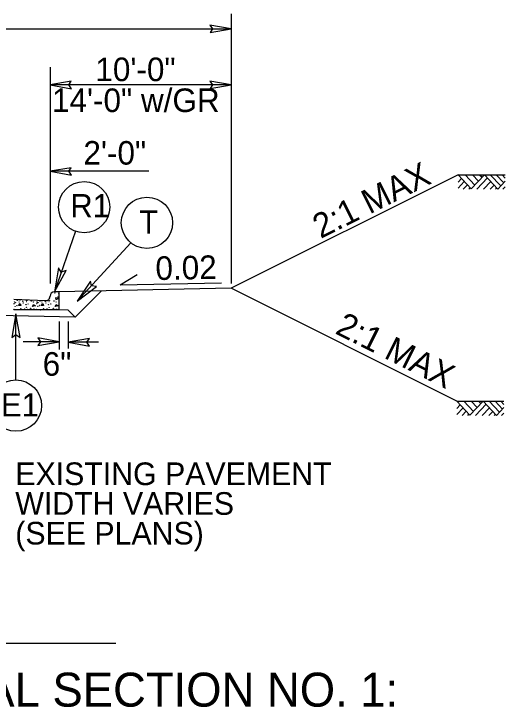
# Model space of a CAD drawing. Extents: x 1904401 to 1905163, y 193929 to 194736.
# Drawn here: x 1904816.27 to 1904843.39, y 194578.77 to 194617.01 of the extents above; entities that cross this region are included whole.
import ezdxf

# ---------------------------------------------------------------- set-up
doc = ezdxf.new("R2010")
doc.units = 0
for name, color, linetype in [('Old_Level_1', 7, 'Continuous'), ('Old_Level_11', 7, 'Continuous'), ('Old_Level_20', 7, 'Continuous'), ('Prop Dimension Text', 7, 'Continuous'), ('Prop Lane Arrow CELL', 7, 'Continuous'), ('Typical Arrow Superelevation CELL', 7, 'Continuous'), ('Typical Berm CELL', 7, 'Continuous'), ('Typical Curb CELL', 7, 'Continuous'), ('Typical Hinge Slope Arterial CELL', 7, 'Continuous'), ('Typical Pavement Slope CELL', 7, 'Continuous'), ('Typical Terminator CELL', 7, 'Continuous')]:
    doc.layers.add(name, color=color, linetype=linetype)

msp = doc.modelspace()

# ---------------------------------------------------------------- linework, layer by layer
at = {"layer": 'Old_Level_1'}
for p, q in [((1904764.772, 194616.184), (1904828.272, 194616.184)), ((1904828.272, 194613.092), (1904818.272, 194613.092)), ((1904823.719, 194608.326), (1904818.272, 194608.326)), ((1904840.792, 194608.132), (1904841.516, 194607.353)), ((1904841.184, 194608.14), (1904841.716, 194607.567)), ((1904841.516, 194607.353), (1904842.247, 194608.139)), ((1904841.582, 194608.14), (1904841.914, 194607.781)), ((1904841.826, 194607.335), (1904842.413, 194607.963)), ((1904841.983, 194608.14), (1904842.117, 194607.997)), ((1904842.247, 194608.139), (1904842.988, 194607.343)), ((1904842.569, 194608.14), (1904843.15, 194607.517)), ((1904842.902, 194608.14), (1904843.317, 194607.696)), ((1904843.223, 194608.14), (1904843.393, 194607.957)), ((1904840.792, 194607.731), (1904840.978, 194607.931)), ((1904840.792, 194607.398), (1904841.135, 194607.764)), ((1904841.081, 194607.335), (1904841.307, 194607.578)), ((1904842.196, 194607.335), (1904842.596, 194607.764)), ((1904842.562, 194607.335), (1904842.78, 194607.568)), ((1904842.988, 194607.343), (1904843.392, 194607.778)), ((1904841.391, 194607.335), (1904841.463, 194607.411)), ((1904842.857, 194607.335), (1904842.927, 194607.409)), ((1904843.258, 194607.335), (1904843.393, 194607.478)), ((1904840.725, 194595.646), (1904841.449, 194594.867)), ((1904840.725, 194595.245), (1904840.911, 194595.445)), ((1904841.116, 194595.654), (1904841.649, 194595.081)), ((1904841.449, 194594.867), (1904842.18, 194595.653)), ((1904841.514, 194595.654), (1904841.847, 194595.295)), ((1904841.759, 194594.849), (1904842.345, 194595.477)), ((1904841.916, 194595.654), (1904842.049, 194595.511)), ((1904842.18, 194595.653), (1904842.921, 194594.857)), ((1904842.502, 194595.654), (1904843.082, 194595.031)), ((1904842.835, 194595.654), (1904843.249, 194595.21)), ((1904843.155, 194595.654), (1904843.325, 194595.471)), ((1904840.725, 194594.912), (1904841.067, 194595.278)), ((1904841.013, 194594.849), (1904841.24, 194595.092)), ((1904842.129, 194594.849), (1904842.529, 194595.278)), ((1904842.495, 194594.849), (1904842.712, 194595.082)), ((1904842.921, 194594.857), (1904843.325, 194595.292)), ((1904843.191, 194594.849), (1904843.325, 194594.992)), ((1904841.324, 194594.849), (1904841.395, 194594.925)), ((1904842.79, 194594.849), (1904842.859, 194594.923)), ((1904769.505, 194582.305), (1904821.899, 194582.305))]:
    msp.add_line(p, q, dxfattribs=at)
for points in [[(1904840.792, 194608.14), (1904843.392, 194608.14)], [(1904840.725, 194595.654), (1904843.325, 194595.654)]]:
    msp.add_lwpolyline(points, dxfattribs=at)
at = {"layer": 'Old_Level_11'}
for p, q in [((1904819.679, 194605.019), (1904818.512, 194601.682)), ((1904822.732, 194604.386), (1904819.776, 194601.157)), ((1904816.389, 194596.816), (1904816.389, 194600.471))]:
    msp.add_line(p, q, dxfattribs=at)
for points in [[(1904818.729, 194602.993), (1904818.512, 194601.682), (1904819.164, 194602.849), (1904818.889, 194602.768)], [(1904820.501, 194602.27), (1904819.776, 194601.157), (1904820.841, 194601.964), (1904820.557, 194602)], [(1904816.615, 194599.161), (1904816.389, 194600.471), (1904816.156, 194599.155), (1904816.389, 194599.322)]]:
    msp.add_lwpolyline(points, close=True, dxfattribs=at)
for centre in [(1904820.156, 194606.35), (1904823.62, 194605.487), (1904816.389, 194595.402)]:
    msp.add_circle(centre, 1.414, dxfattribs=at)
at = {"layer": 'Prop Dimension Text'}
for p, q in [((1904828.272, 194617.012), (1904828.272, 194602.146)), ((1904818.272, 194614.065), (1904818.272, 194602.146))]:
    msp.add_line(p, q, dxfattribs=at)
at = {"layer": 'Prop Lane Arrow CELL'}
for p, q in [((1904818.772, 194600.042), (1904818.772, 194598.503)), ((1904819.272, 194600.041), (1904819.272, 194598.543)), ((1904818.772, 194598.925), (1904816.782, 194598.925)), ((1904820.943, 194598.897), (1904819.272, 194598.897))]:
    msp.add_line(p, q, dxfattribs=at)
at = {"layer": 'Typical Arrow Superelevation CELL'}
for q in [(1904823.089, 194602.629), (1904827.742, 194602.173)]:
    msp.add_line((1904822.149, 194602.061), q, dxfattribs=at)
at = {"layer": 'Typical Berm CELL'}
msp.add_line((1904828.272, 194601.88), (1904818.772, 194601.682), dxfattribs=at)
at = {"layer": 'Typical Curb CELL'}
for p, q in [((1904818.272, 194601.432), (1904818.272, 194601.443)), ((1904818.772, 194601.682), (1904818.512, 194601.682)), ((1904818.772, 194600.682), (1904818.772, 194601.682)), ((1904816.272, 194601.266), (1904818.023, 194601.193)), ((1904818.581, 194601.349), (1904818.598, 194601.258)), ((1904818.736, 194601.304), (1904818.581, 194601.349)), ((1904818.598, 194601.258), (1904818.736, 194601.304)), ((1904818.772, 194600.682), (1904816.272, 194600.682)), ((1904816.533, 194600.922), (1904816.619, 194601.042)), ((1904816.654, 194600.928), (1904816.533, 194600.922)), ((1904816.619, 194601.042), (1904816.654, 194600.928)), ((1904817.298, 194600.871), (1904817.361, 194600.985)), ((1904817.464, 194600.91), (1904817.298, 194600.871)), ((1904817.361, 194600.985), (1904817.464, 194600.91)), ((1904817.783, 194600.922), (1904817.868, 194601.042)), ((1904817.902, 194600.928), (1904817.783, 194600.922)), ((1904817.868, 194601.042), (1904817.902, 194600.928)), ((1904818.547, 194600.871), (1904818.61, 194600.985)), ((1904818.713, 194600.91), (1904818.547, 194600.871)), ((1904818.61, 194600.985), (1904818.713, 194600.91))]:
    msp.add_line(p, q, dxfattribs=at)
for centre in [(1904818.542, 194601.606), (1904818.759, 194601.572), (1904816.306, 194601.116), (1904816.362, 194601.082), (1904816.471, 194601.207), (1904816.568, 194601.122), (1904816.613, 194601.224), (1904816.762, 194601.161), (1904816.79, 194601.059), (1904816.967, 194601.145), (1904816.984, 194601.195), (1904817.241, 194601.167), (1904817.361, 194601.116), (1904817.555, 194601.116), (1904817.611, 194601.082), (1904817.72, 194601.176), (1904817.817, 194601.122), (1904818.011, 194601.161), (1904818.039, 194601.059), (1904818.216, 194601.145), (1904818.233, 194601.195), (1904818.49, 194601.167), (1904818.61, 194601.116), (1904818.707, 194601.389), (1904816.283, 194600.711), (1904816.289, 194601.019), (1904816.346, 194600.877), (1904816.442, 194600.922), (1904816.494, 194600.688), (1904816.653, 194600.757), (1904816.859, 194600.734), (1904816.939, 194600.974), (1904816.973, 194600.82), (1904817.03, 194600.705), (1904817.064, 194601.002), (1904817.207, 194600.768), (1904817.378, 194600.728), (1904817.532, 194600.711), (1904817.538, 194601.019), (1904817.595, 194600.877), (1904817.691, 194600.922), (1904817.743, 194600.688), (1904817.902, 194600.757), (1904818.108, 194600.734), (1904818.188, 194600.974), (1904818.222, 194600.82), (1904818.279, 194600.705), (1904818.313, 194601.002), (1904818.456, 194600.768), (1904818.627, 194600.728)]:
    msp.add_circle(centre, 0.00802, dxfattribs=at)
for centre, start, end in [((1904818.512, 194601.443), 90, 180), ((1904818.033, 194601.432), 267.6155, 0)]:
    msp.add_arc(centre, 0.24, start, end, dxfattribs=at)
at = {"layer": 'Typical Hinge Slope Arterial CELL'}
for p in [(1904840.792, 194608.14), (1904840.725, 194595.654)]:
    msp.add_line(p, (1904828.272, 194601.88), dxfattribs=at)
at = {"layer": 'Typical Pavement Slope CELL'}
for p, q in [((1904819.663, 194600.281), (1904821.113, 194601.731)), ((1904819.272, 194600.672), (1904818.772, 194600.682)), ((1904819.663, 194600.281), (1904819.272, 194600.672)), ((1904819.663, 194600.281), (1904810.011, 194600.474))]:
    msp.add_line(p, q, dxfattribs=at)
at = {"layer": 'Typical Terminator CELL'}
for points in [[(1904827.101, 194615.983), (1904828.272, 194616.184), (1904827.094, 194616.393), (1904827.244, 194616.184)], [(1904819.444, 194613.294), (1904818.272, 194613.092), (1904819.451, 194612.884), (1904819.301, 194613.092)], [(1904827.101, 194612.89), (1904828.272, 194613.092), (1904827.094, 194613.3), (1904827.244, 194613.092)], [(1904819.444, 194608.527), (1904818.272, 194608.326), (1904819.451, 194608.117), (1904819.301, 194608.326)], [(1904817.6, 194598.723), (1904818.772, 194598.925), (1904817.594, 194599.133), (1904817.744, 194598.925)], [(1904820.444, 194599.099), (1904819.272, 194598.897), (1904820.45, 194598.689), (1904820.3, 194598.897)]]:
    msp.add_lwpolyline(points, close=True, dxfattribs=at)

# ---------------------------------------------------------------- texts
at = {"layer": 'Old_Level_1'}
for s, height, p in [('10\'-0"', 1.3, (1904820.774, 194613.3)), ('14\'-0" w/GR', 1.3, (1904818.377, 194611.596)), ('2\'-0" ', 1.3, (1904820.114, 194608.694)), ('6" ', 1.3, (1904817.866, 194597.051)), ('TRANSITION FROM EXISTING TO TYPICAL SECTION NO. 1:', 1.875, (1904766.722, 194578.794))]:
    msp.add_text(s, height=height, dxfattribs=at).set_placement(p)
at = {"layer": 'Old_Level_20'}
for s, height, p in [('R1', 1.2792, (1904819.391, 194605.791)), ('T', 1.279, (1904823.192, 194604.89)), ('E1', 1.2792, (1904815.563, 194594.805))]:
    msp.add_text(s, height=height, dxfattribs=at).set_placement(p)
at = {"layer": 'Prop Dimension Text'}
msp.add_text('0.02', height=1.3, rotation=1.1462, dxfattribs=at).set_placement((1904824.101, 194602.327))
at = {"layer": 'Prop Lane Arrow CELL'}
for s, p in [('EXISTING PAVEMENT', (1904816.354, 194591.016)), ('WIDTH VARIES', (1904816.354, 194589.377)), ('(SEE PLANS)', (1904816.354, 194587.739))]:
    msp.add_text(s, height=1.25, dxfattribs=at).set_placement(p)
at = {"layer": 'Typical Hinge Slope Arterial CELL'}
for rotation, p in [(26.5651, (1904833.208, 194604.587)), (333.435, (1904833.953, 194599.4))]:
    msp.add_text('2:1 MAX', height=1.35, rotation=rotation, dxfattribs=at).set_placement(p)

doc.saveas('drawing.dxf')
